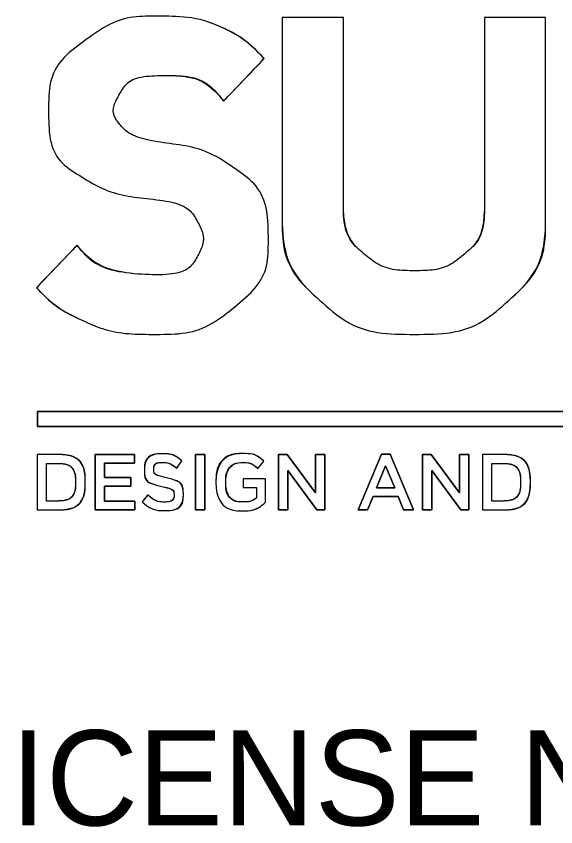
# Model space of a CAD drawing. Extents: x 2787886 to 2789612, y 1113277 to 1114394.
# Drawn here: x 2789506.2 to 2789528.35, y 1114082.77 to 1114116.06 of the extents above; entities that cross this region are included whole.
import ezdxf

# ---------------------------------------------------------------- set-up
doc = ezdxf.new("R2010")
doc.units = 0
doc.layers.add('Sheet Plan CELL', color=7, linetype='Continuous')

msp = doc.modelspace()

# ---------------------------------------------------------------- linework, layer by layer
at = {"layer": 'Sheet Plan CELL'}
for p, q in [((2789514.712, 1114112.581), (2789516.383, 1114114.322)), ((2789508.696, 1114106.656), (2789507.025, 1114104.914)), ((2789512.788, 1114097.504), (2789512.994, 1114097.806)), ((2789516.119, 1114097.488), (2789516.361, 1114097.79)), ((2789511.46, 1114097.433), (2789511.46, 1114097.427)), ((2789511.842, 1114097.462), (2789511.842, 1114097.469)), ((2789508.631, 1114096.923), (2789508.631, 1114096.917)), ((2789509.032, 1114096.923), (2789509.032, 1114096.93)), ((2789514.4, 1114096.923), (2789514.4, 1114096.917)), ((2789514.802, 1114096.923), (2789514.802, 1114096.93)), ((2789526.909, 1114096.923), (2789526.909, 1114096.917)), ((2789527.311, 1114096.923), (2789527.311, 1114096.93)), ((2789511.602, 1114096.404), (2789511.372, 1114096.118)), ((2789512.677, 1114096.401), (2789512.677, 1114096.394)), ((2789513.059, 1114096.433), (2789513.059, 1114096.44))]:
    msp.add_line(p, q, dxfattribs=at)
for points in [[(2789519.631, 1114108.487), (2789519.631, 1114116.012), (2789517.119, 1114116.012), (2789517.119, 1114107.789)], [(2789527.938, 1114107.789), (2789527.938, 1114116.012), (2789525.427, 1114116.012), (2789525.427, 1114108.487)], [(2789567.93, 1114099.218), (2789507.073, 1114099.218), (2789507.073, 1114099.822), (2789567.93, 1114099.822), (2789567.93, 1114099.218)], [(2789567.93, 1114099.822), (2789507.073, 1114099.822), (2789507.073, 1114099.218), (2789567.93, 1114099.218), (2789567.93, 1114099.822)], [(2789507.874, 1114098.059), (2789507.062, 1114098.059), (2789507.062, 1114095.787), (2789507.874, 1114095.787)], [(2789509.433, 1114098.059), (2789511.049, 1114098.059), (2789511.049, 1114097.702), (2789509.816, 1114097.702), (2789509.816, 1114097.112), (2789510.909, 1114097.112), (2789510.909, 1114096.755), (2789509.816, 1114096.755), (2789509.816, 1114096.145), (2789511.064, 1114096.145), (2789511.064, 1114095.787), (2789509.433, 1114095.787), (2789509.433, 1114098.059)], [(2789509.433, 1114095.787), (2789511.064, 1114095.787), (2789511.064, 1114096.145), (2789509.816, 1114096.145), (2789509.816, 1114096.755), (2789510.909, 1114096.755), (2789510.909, 1114097.112), (2789509.816, 1114097.112), (2789509.816, 1114097.702), (2789511.049, 1114097.702), (2789511.049, 1114098.059), (2789509.433, 1114098.059), (2789509.433, 1114095.787)], [(2789513.563, 1114098.059), (2789513.946, 1114098.059), (2789513.946, 1114095.787), (2789513.563, 1114095.787), (2789513.563, 1114098.059)], [(2789513.563, 1114095.787), (2789513.946, 1114095.787), (2789513.946, 1114098.059), (2789513.563, 1114098.059), (2789513.563, 1114095.787)], [(2789516.968, 1114098.059), (2789517.323, 1114098.059), (2789518.49, 1114096.489), (2789518.49, 1114098.059), (2789518.867, 1114098.059), (2789518.867, 1114095.787), (2789518.546, 1114095.787), (2789517.345, 1114097.404), (2789517.345, 1114095.787), (2789516.968, 1114095.787), (2789516.968, 1114098.059)], [(2789516.968, 1114095.787), (2789517.345, 1114095.787), (2789517.345, 1114097.404), (2789518.546, 1114095.787), (2789518.867, 1114095.787), (2789518.867, 1114098.059), (2789518.49, 1114098.059), (2789518.49, 1114096.489), (2789517.323, 1114098.059), (2789516.968, 1114098.059), (2789516.968, 1114095.787)], [(2789521.195, 1114098.076), (2789521.55, 1114098.076), (2789522.509, 1114095.787), (2789522.104, 1114095.787), (2789521.882, 1114096.336), (2789520.852, 1114096.336), (2789520.628, 1114095.787), (2789520.236, 1114095.787), (2789521.195, 1114098.076)], [(2789520.236, 1114095.787), (2789520.628, 1114095.787), (2789520.852, 1114096.336), (2789521.882, 1114096.336), (2789522.104, 1114095.787), (2789522.509, 1114095.787), (2789521.55, 1114098.076), (2789521.195, 1114098.076), (2789520.236, 1114095.787)], [(2789522.881, 1114098.059), (2789523.236, 1114098.059), (2789524.403, 1114096.489), (2789524.403, 1114098.059), (2789524.78, 1114098.059), (2789524.78, 1114095.787), (2789524.46, 1114095.787), (2789523.258, 1114097.404), (2789523.258, 1114095.787), (2789522.881, 1114095.787), (2789522.881, 1114098.059)], [(2789522.881, 1114095.787), (2789523.258, 1114095.787), (2789523.258, 1114097.404), (2789524.46, 1114095.787), (2789524.78, 1114095.787), (2789524.78, 1114098.059), (2789524.403, 1114098.059), (2789524.403, 1114096.489), (2789523.236, 1114098.059), (2789522.881, 1114098.059), (2789522.881, 1114095.787)], [(2789526.153, 1114098.059), (2789525.34, 1114098.059), (2789525.34, 1114095.787), (2789526.153, 1114095.787)], [(2789507.874, 1114096.151), (2789507.445, 1114096.151), (2789507.445, 1114097.696), (2789507.874, 1114097.696)], [(2789521.743, 1114096.69), (2789521.366, 1114097.598), (2789520.992, 1114096.69), (2789521.743, 1114096.69)], [(2789520.992, 1114096.69), (2789521.366, 1114097.598), (2789521.743, 1114096.69), (2789520.992, 1114096.69)], [(2789526.153, 1114096.151), (2789525.723, 1114096.151), (2789525.723, 1114097.696), (2789526.153, 1114097.696)], [(2789516.439, 1114096.102), (2789516.439, 1114097.056), (2789515.512, 1114097.056), (2789515.512, 1114096.709), (2789516.069, 1114096.709), (2789516.069, 1114096.284)]]:
    msp.add_lwpolyline(points, dxfattribs=at)
for points, degree in [([(2789514.586, 1114115.629), (2789515.227, 1114115.339), (2789515.826, 1114114.904), (2789516.383, 1114114.322), (2789516.383, 1114114.322), (2789514.712, 1114112.581), (2789514.712, 1114112.581), (2789514.154, 1114113.277), (2789513.375, 1114113.626), (2789512.372, 1114113.626), (2789511.37, 1114113.626), (2789510.729, 1114113.379), (2789510.45, 1114112.885), (2789510.172, 1114112.391), (2789510.172, 1114111.971), (2789510.45, 1114111.622), (2789510.729, 1114111.273), (2789511.37, 1114111.012), (2789512.372, 1114110.838), (2789513.43, 1114110.722), (2789514.392, 1114110.359), (2789515.255, 1114109.749), (2789516.118, 1114109.14), (2789516.55, 1114108.167), (2789516.55, 1114106.831), (2789516.55, 1114105.785), (2789516.089, 1114104.885), (2789515.167, 1114104.13), (2789514.246, 1114103.375), (2789513.172, 1114102.997), (2789511.945, 1114102.997), (2789510.782, 1114102.997), (2789509.81, 1114103.172), (2789509.029, 1114103.52), (2789508.249, 1114103.869), (2789507.582, 1114104.334), (2789507.025, 1114104.914), (2789507.025, 1114104.914), (2789508.696, 1114106.656), (2789508.696, 1114106.656), (2789509.253, 1114105.959), (2789510.2, 1114105.553), (2789511.537, 1114105.437), (2789512.651, 1114105.437), (2789513.346, 1114105.684), (2789513.622, 1114106.178), (2789513.897, 1114106.671), (2789513.897, 1114107.164), (2789513.622, 1114107.658), (2789513.346, 1114108.152), (2789512.651, 1114108.456), (2789511.537, 1114108.573), (2789510.534, 1114108.689), (2789509.615, 1114109.008), (2789508.779, 1114109.531), (2789507.944, 1114110.054), (2789507.526, 1114110.954), (2789507.526, 1114112.232), (2789507.526, 1114113.387), (2789508.001, 1114114.315), (2789508.951, 1114115.015), (2789509.9, 1114115.716), (2789510.876, 1114116.065), (2789511.879, 1114116.065), (2789513.043, 1114116.065), (2789513.946, 1114115.92), (2789514.586, 1114115.629)], 3), ([(2789514.586, 1114115.629), (2789513.946, 1114115.92), (2789513.043, 1114116.065), (2789511.879, 1114116.065), (2789510.876, 1114116.065), (2789509.9, 1114115.716), (2789508.951, 1114115.015), (2789508.001, 1114114.315), (2789507.526, 1114113.387), (2789507.526, 1114112.232), (2789507.526, 1114110.954), (2789507.944, 1114110.054), (2789508.779, 1114109.531), (2789509.615, 1114109.008), (2789510.534, 1114108.689), (2789511.537, 1114108.573), (2789512.651, 1114108.456), (2789513.346, 1114108.152), (2789513.622, 1114107.658), (2789513.897, 1114107.164), (2789513.897, 1114106.671), (2789513.622, 1114106.178), (2789513.346, 1114105.684), (2789512.651, 1114105.437), (2789511.537, 1114105.437), (2789510.2, 1114105.553), (2789509.253, 1114105.959), (2789508.696, 1114106.656)], 3), ([(2789519.631, 1114116.012), (2789519.631, 1114116.012), (2789519.631, 1114108.487), (2789519.631, 1114108.487), (2789519.631, 1114107.498), (2789519.916, 1114106.773), (2789520.472, 1114106.308), (2789521.03, 1114105.843), (2789521.729, 1114105.611), (2789522.565, 1114105.611), (2789523.4, 1114105.611), (2789524.066, 1114105.843), (2789524.623, 1114106.308), (2789525.18, 1114106.773), (2789525.427, 1114107.498), (2789525.427, 1114108.487), (2789525.427, 1114108.487), (2789525.427, 1114116.012), (2789525.427, 1114116.012), (2789525.427, 1114116.012), (2789527.938, 1114116.012), (2789527.938, 1114116.012), (2789527.938, 1114116.012), (2789527.938, 1114107.789), (2789527.938, 1114107.789), (2789527.938, 1114106.453), (2789527.454, 1114105.321), (2789526.423, 1114104.392), (2789525.392, 1114103.463), (2789524.113, 1114102.997), (2789522.553, 1114102.997), (2789520.993, 1114102.997), (2789519.696, 1114103.463), (2789518.666, 1114104.392), (2789517.635, 1114105.321), (2789517.119, 1114106.453), (2789517.119, 1114107.789), (2789517.119, 1114107.789), (2789517.119, 1114116.012), (2789517.119, 1114116.012), (2789517.119, 1114116.012), (2789519.631, 1114116.012), (2789519.631, 1114116.012)], 3), ([(2789516.383, 1114114.322), (2789515.826, 1114114.904), (2789515.227, 1114115.339), (2789514.586, 1114115.629)], 2), ([(2789507.025, 1114104.914), (2789507.582, 1114104.334), (2789508.249, 1114103.869), (2789509.029, 1114103.52), (2789509.81, 1114103.172), (2789510.782, 1114102.997), (2789511.945, 1114102.997), (2789513.172, 1114102.997), (2789514.246, 1114103.375), (2789515.167, 1114104.13), (2789516.089, 1114104.885), (2789516.55, 1114105.785), (2789516.55, 1114106.831), (2789516.55, 1114108.167), (2789516.118, 1114109.14), (2789515.255, 1114109.749), (2789514.392, 1114110.359), (2789513.43, 1114110.722), (2789512.372, 1114110.838), (2789511.37, 1114111.012), (2789510.729, 1114111.273), (2789510.45, 1114111.622), (2789510.172, 1114111.971), (2789510.172, 1114112.391), (2789510.45, 1114112.885), (2789510.729, 1114113.379), (2789511.37, 1114113.626), (2789512.372, 1114113.626), (2789513.375, 1114113.626), (2789514.154, 1114113.277), (2789514.712, 1114112.581)], 3), ([(2789525.427, 1114108.487), (2789525.427, 1114107.498), (2789525.18, 1114106.773), (2789524.623, 1114106.308), (2789524.066, 1114105.843), (2789523.4, 1114105.611), (2789522.565, 1114105.611), (2789521.729, 1114105.611), (2789521.03, 1114105.843), (2789520.472, 1114106.308), (2789519.916, 1114106.773), (2789519.631, 1114107.498), (2789519.631, 1114108.487)], 3), ([(2789517.119, 1114107.789), (2789517.119, 1114106.453), (2789517.635, 1114105.321), (2789518.666, 1114104.392), (2789519.696, 1114103.463), (2789520.993, 1114102.997), (2789522.553, 1114102.997), (2789524.113, 1114102.997), (2789525.392, 1114103.463), (2789526.423, 1114104.392), (2789527.454, 1114105.321), (2789527.938, 1114106.453), (2789527.938, 1114107.789)], 3), ([(2789507.062, 1114098.059), (2789507.062, 1114098.059), (2789507.874, 1114098.059), (2789507.874, 1114098.059), (2789508.559, 1114098.059), (2789509.032, 1114097.569), (2789509.032, 1114096.93), (2789509.032, 1114096.93), (2789509.032, 1114096.923), (2789509.032, 1114096.923), (2789509.032, 1114096.284), (2789508.559, 1114095.787), (2789507.874, 1114095.787), (2789507.874, 1114095.787), (2789507.062, 1114095.787), (2789507.062, 1114095.787), (2789507.062, 1114095.787), (2789507.062, 1114098.059), (2789507.062, 1114098.059)], 3), ([(2789509.032, 1114096.93), (2789509.032, 1114097.569), (2789508.559, 1114098.059), (2789507.874, 1114098.059)], 2), ([(2789511.372, 1114096.118), (2789511.372, 1114096.118), (2789511.602, 1114096.404), (2789511.602, 1114096.404), (2789511.811, 1114096.216), (2789512.023, 1114096.109), (2789512.291, 1114096.109), (2789512.527, 1114096.109), (2789512.677, 1114096.226), (2789512.677, 1114096.394), (2789512.677, 1114096.394), (2789512.677, 1114096.401), (2789512.677, 1114096.401), (2789512.677, 1114096.563), (2789512.589, 1114096.651), (2789512.185, 1114096.748), (2789511.721, 1114096.865), (2789511.46, 1114097.008), (2789511.46, 1114097.427), (2789511.46, 1114097.427), (2789511.46, 1114097.433), (2789511.46, 1114097.433), (2789511.46, 1114097.823), (2789511.771, 1114098.092), (2789512.203, 1114098.092), (2789512.521, 1114098.092), (2789512.773, 1114097.991), (2789512.994, 1114097.806), (2789512.994, 1114097.806), (2789512.788, 1114097.504), (2789512.788, 1114097.504), (2789512.593, 1114097.657), (2789512.397, 1114097.738), (2789512.197, 1114097.738), (2789511.973, 1114097.738), (2789511.842, 1114097.618), (2789511.842, 1114097.469), (2789511.842, 1114097.469), (2789511.842, 1114097.462), (2789511.842, 1114097.462), (2789511.842, 1114097.287), (2789511.942, 1114097.209), (2789512.362, 1114097.105), (2789512.823, 1114096.988), (2789513.059, 1114096.816), (2789513.059, 1114096.44), (2789513.059, 1114096.44), (2789513.059, 1114096.433), (2789513.059, 1114096.433), (2789513.059, 1114096.008), (2789512.739, 1114095.755), (2789512.281, 1114095.755), (2789511.948, 1114095.755), (2789511.634, 1114095.875), (2789511.372, 1114096.118)], 3), ([(2789512.994, 1114097.806), (2789512.773, 1114097.991), (2789512.521, 1114098.092), (2789512.203, 1114098.092), (2789511.771, 1114098.092), (2789511.46, 1114097.823), (2789511.46, 1114097.433)], 3), ([(2789514.4, 1114096.917), (2789514.4, 1114096.917), (2789514.4, 1114096.923), (2789514.4, 1114096.923), (2789514.4, 1114097.56), (2789514.867, 1114098.098), (2789515.524, 1114098.098), (2789515.904, 1114098.098), (2789516.137, 1114097.988), (2789516.361, 1114097.79), (2789516.361, 1114097.79), (2789516.119, 1114097.488), (2789516.119, 1114097.488), (2789515.95, 1114097.637), (2789515.786, 1114097.732), (2789515.509, 1114097.732), (2789515.107, 1114097.732), (2789514.802, 1114097.365), (2789514.802, 1114096.93), (2789514.802, 1114096.93), (2789514.802, 1114096.923), (2789514.802, 1114096.923), (2789514.802, 1114096.456), (2789515.098, 1114096.112), (2789515.543, 1114096.112), (2789515.748, 1114096.112), (2789515.935, 1114096.18), (2789516.069, 1114096.284), (2789516.069, 1114096.284), (2789516.069, 1114096.709), (2789516.069, 1114096.709), (2789516.069, 1114096.709), (2789515.512, 1114096.709), (2789515.512, 1114096.709), (2789515.512, 1114096.709), (2789515.512, 1114097.056), (2789515.512, 1114097.056), (2789515.512, 1114097.056), (2789516.439, 1114097.056), (2789516.439, 1114097.056), (2789516.439, 1114097.056), (2789516.439, 1114096.102), (2789516.439, 1114096.102), (2789516.225, 1114095.911), (2789515.916, 1114095.748), (2789515.53, 1114095.748), (2789514.849, 1114095.748), (2789514.4, 1114096.255), (2789514.4, 1114096.917)], 3), ([(2789516.361, 1114097.79), (2789516.137, 1114097.988), (2789515.904, 1114098.098), (2789515.524, 1114098.098), (2789514.867, 1114098.098), (2789514.4, 1114097.56), (2789514.4, 1114096.923)], 3), ([(2789525.34, 1114098.059), (2789525.34, 1114098.059), (2789526.153, 1114098.059), (2789526.153, 1114098.059), (2789526.837, 1114098.059), (2789527.311, 1114097.569), (2789527.311, 1114096.93), (2789527.311, 1114096.93), (2789527.311, 1114096.923), (2789527.311, 1114096.923), (2789527.311, 1114096.284), (2789526.837, 1114095.787), (2789526.153, 1114095.787), (2789526.153, 1114095.787), (2789525.34, 1114095.787), (2789525.34, 1114095.787), (2789525.34, 1114095.787), (2789525.34, 1114098.059), (2789525.34, 1114098.059)], 3), ([(2789527.311, 1114096.93), (2789527.311, 1114097.569), (2789526.837, 1114098.059), (2789526.153, 1114098.059)], 2), ([(2789511.842, 1114097.469), (2789511.842, 1114097.618), (2789511.973, 1114097.738), (2789512.197, 1114097.738), (2789512.397, 1114097.738), (2789512.593, 1114097.657), (2789512.788, 1114097.504)], 3), ([(2789514.802, 1114096.93), (2789514.802, 1114097.365), (2789515.107, 1114097.732), (2789515.509, 1114097.732), (2789515.786, 1114097.732), (2789515.95, 1114097.637), (2789516.119, 1114097.488)], 3), ([(2789507.445, 1114097.696), (2789507.445, 1114097.696), (2789507.445, 1114096.151), (2789507.445, 1114096.151), (2789507.445, 1114096.151), (2789507.874, 1114096.151), (2789507.874, 1114096.151), (2789508.332, 1114096.151), (2789508.631, 1114096.472), (2789508.631, 1114096.917), (2789508.631, 1114096.917), (2789508.631, 1114096.923), (2789508.631, 1114096.923), (2789508.631, 1114097.368), (2789508.332, 1114097.696), (2789507.874, 1114097.696), (2789507.874, 1114097.696), (2789507.445, 1114097.696), (2789507.445, 1114097.696)], 3), ([(2789507.874, 1114097.696), (2789508.332, 1114097.696), (2789508.631, 1114097.368), (2789508.631, 1114096.923)], 2), ([(2789511.46, 1114097.427), (2789511.46, 1114097.008), (2789511.721, 1114096.865), (2789512.185, 1114096.748), (2789512.589, 1114096.651), (2789512.677, 1114096.563), (2789512.677, 1114096.401)], 3), ([(2789513.059, 1114096.44), (2789513.059, 1114096.816), (2789512.823, 1114096.988), (2789512.362, 1114097.105), (2789511.942, 1114097.209), (2789511.842, 1114097.287), (2789511.842, 1114097.462)], 3), ([(2789525.723, 1114097.696), (2789525.723, 1114097.696), (2789525.723, 1114096.151), (2789525.723, 1114096.151), (2789525.723, 1114096.151), (2789526.153, 1114096.151), (2789526.153, 1114096.151), (2789526.61, 1114096.151), (2789526.909, 1114096.472), (2789526.909, 1114096.917), (2789526.909, 1114096.917), (2789526.909, 1114096.923), (2789526.909, 1114096.923), (2789526.909, 1114097.368), (2789526.61, 1114097.696), (2789526.153, 1114097.696), (2789526.153, 1114097.696), (2789525.723, 1114097.696), (2789525.723, 1114097.696)], 3), ([(2789526.153, 1114097.696), (2789526.61, 1114097.696), (2789526.909, 1114097.368), (2789526.909, 1114096.923)], 2), ([(2789507.874, 1114095.787), (2789508.559, 1114095.787), (2789509.032, 1114096.284), (2789509.032, 1114096.923)], 2), ([(2789508.631, 1114096.917), (2789508.631, 1114096.472), (2789508.332, 1114096.151), (2789507.874, 1114096.151)], 2), ([(2789514.4, 1114096.917), (2789514.4, 1114096.255), (2789514.849, 1114095.748), (2789515.53, 1114095.748), (2789515.916, 1114095.748), (2789516.225, 1114095.911), (2789516.439, 1114096.102)], 3), ([(2789516.069, 1114096.284), (2789515.935, 1114096.18), (2789515.748, 1114096.112), (2789515.543, 1114096.112), (2789515.098, 1114096.112), (2789514.802, 1114096.456), (2789514.802, 1114096.923)], 3), ([(2789526.153, 1114095.787), (2789526.837, 1114095.787), (2789527.311, 1114096.284), (2789527.311, 1114096.923)], 2), ([(2789526.909, 1114096.917), (2789526.909, 1114096.472), (2789526.61, 1114096.151), (2789526.153, 1114096.151)], 2), ([(2789511.372, 1114096.118), (2789511.634, 1114095.875), (2789511.948, 1114095.755), (2789512.281, 1114095.755), (2789512.739, 1114095.755), (2789513.059, 1114096.008), (2789513.059, 1114096.433)], 3), ([(2789512.677, 1114096.394), (2789512.677, 1114096.226), (2789512.527, 1114096.109), (2789512.291, 1114096.109), (2789512.023, 1114096.109), (2789511.811, 1114096.216), (2789511.602, 1114096.404)], 3)]:
    msp.add_open_spline(points, degree=degree, dxfattribs=at)

# ---------------------------------------------------------------- texts
msp.add_text('NC FIRM LICENSE No: C-5176', height=3.9085, rotation=360, dxfattribs=at).set_placement((2789479.836, 1114082.825))

doc.saveas('drawing.dxf')
